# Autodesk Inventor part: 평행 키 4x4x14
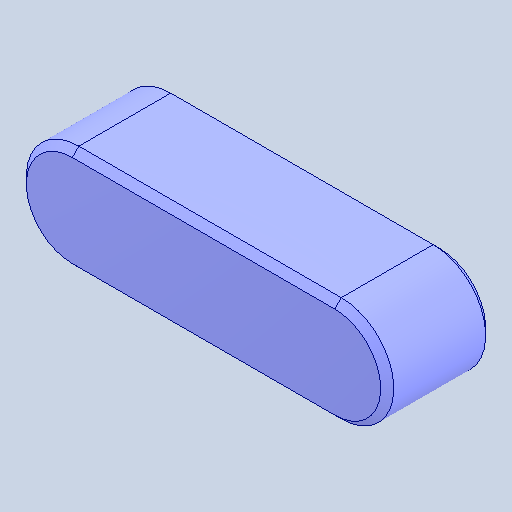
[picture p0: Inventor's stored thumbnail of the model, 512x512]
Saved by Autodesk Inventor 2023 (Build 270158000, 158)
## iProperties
Created: 2026-03
Part Number: 평행 키 4x4x14
Material: 강철, 연강
Description: 키 및 해당 키홈
Document SubType Name: Modeling
Designer: 4강의실
Density: 7.85 g/cm^3
Appearance: 기본값
Author: jhkim
Sending System: Autodesk Inventor 2026
Preprocessor: ST-DEVELOPER v20.1
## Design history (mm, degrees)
feature "Solid1"
node "솔리드1"
